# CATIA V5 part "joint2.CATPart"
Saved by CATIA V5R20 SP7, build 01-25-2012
Part number: joint2
Bounding box of the stored display mesh (mm): x 306.35 to 501.44, y -23 to 23, z 366.216 to 412.367
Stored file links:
  D:\thinkmotion-MPB\Dropbox\Pack 1 sylvain\CFAO_2010_yyang\yyang\CFAO_2010_yyang\joint2.CATPart
  D:\thinkmotion-MPB\Dropbox\Pack 1 sylvain\CFAO_2010_yyang\yyang\CFAO_2010_yyang\yyang.CATProduct
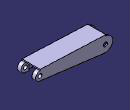
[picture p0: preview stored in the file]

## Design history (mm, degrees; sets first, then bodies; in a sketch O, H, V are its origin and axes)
External parameters (linked from other documents)
  `External.rayon du trou des liaisons` = 5 mm
  `External.rayon plus petit` = 11 mm
  `External.rayon plus grand` = 18 mm
  `External.epaisseur du joint` = 3 mm
  `External.epaisseur de l'oreille` = 3 mm
  `External.demi_distance entre les oreilles` = 15 mm
  `External.longeur du poche plus petit` = 20 mm
  `External.demi_distance entre pivots en haut` = 11 mm
  `External.epaisseur du pivot en haut` = 3 mm
  `External.epaisseur du pivot` = 2 mm
Set1
  Plane1: linked copy from another document
  Point1: linked copy from another document
  Point2: linked copy from another document
Body1 (main body)
  Sketch1 on Plane1, origin (0, 0, 0), H (-1, 0, 0), V (0, 0, 1)
    circle A1 centre (-324.3472, 384.215) radius 5
    point P1 (-324.3472, 384.215)
    reference projected point E1 (-324.3472, 384.215) from Point1
    reference projected point E2 (-324.3472, 384.215) from Point1
    circle A2 centre (-490.4395, 398.3802) radius 5
    point P2 (-490.4395, 398.3802)
    reference projected point E3 (-490.4395, 398.3802) from Point2
    reference projected point E4 (-490.4395, 398.3802) from Point2
    arc A3 centre (-324.3472, 384.215) radius 18 from (-326.6285, 366.3602) to (-323.5721, 402.1983) ccw
    point P3 (-324.3472, 384.215)
    arc A4 centre (-490.4395, 398.3802) radius 11 from (-489.9659, 409.37) to (-491.8337, 387.4689) ccw
    point P4 (-490.4395, 398.3802)
    reference projected point E5 (-490.4395, 398.3802) from Point2
    reference projected point E6 (-490.4395, 398.3802) from Point2
    reference projected point E7 (-324.3472, 384.215) from Point1
    reference projected point E8 (-324.3472, 384.215) from Point1
    axis line L1 (-489.9659, 409.37) -> (-323.5721, 402.1983)
    line L2 (-491.8337, 387.4689) -> (-326.6285, 366.3602)
    line L3 (-489.8367, 412.3672) -> (-323.4429, 405.1956)
    line L4 (-489.9659, 409.37) -> (-489.8367, 412.3672)
    line L5 (-323.5721, 402.1983) -> (-323.4429, 405.1956)
    distance A1 E2 = 5 {= `External.rayon du trou des liaisons`}
    distance A2 E4 = 5 {= `External.rayon du trou des liaisons`}
    distance A4 E6 = 11 {= `External.rayon plus petit`}
    distance A3 E8 = 18 {= `External.rayon plus grand`}
    distance L3 L1 = 3 {= `External.epaisseur du joint`}
    coincidence: P1 E1, P2 E3, P4 E5, P3 E7
    tangency: L1 A3, L1 A4, L2 A4, L2 A3
    perpendicularity: L4 L3, L5 L3
  Pad1: profile Sketch1, direction (0, 1, 0), length 23 {= `External.epaisseur du joint`+`External.epaisseur de l'oreille`+`External.demi_distance entre les oreilles`+`External.epaisseur du pivot`}, mirrored extent
  Sketch2 on Plane1, origin (0, 0, 0), H (-1, 0, 0), V (0, 0, 1)
    line L1 (-481.4395, 409.0025) -> (-481.4395, 386.1408)
    line L2 (-481.4395, 409.0025) -> (-501.4395, 409.8645)
    line L3 (-501.4395, 409.8645) -> (-501.4395, 388.6962)
    reference projected arc E1 centre (-490.4395, 398.3802) radius 11 from (-490.7705, 409.3752) to (-490.7705, 387.3851) ccw from edge [face of Pad1 from Sketch1.A4 | end face of Pad1]
    line L4 (-481.4395, 386.1408) -> (-501.4395, 388.6962)
    reference projected line E2 (-488.8457, 387.0871) -> (-324.053, 366.0311) from edge [face of Pad1 from Sketch1.L2 | end face of Pad1]
    reference projected line E3 (-321.7093, 405.1208) -> (-488.1021, 412.2924) from edge [face of Pad1 from Sketch1.L3 | end face of Pad1]
    reference projected line E4 (-321.7093, 405.1208) -> (-488.1021, 412.2924) from edge [face of Pad1 from Sketch1.L3 | end face of Pad1]
    distance L1 L3 = 20 {= `External.longeur du poche plus petit`}
    distance E4 L2 = 3 {= `External.epaisseur du joint`}
    vertical: L1 V
    tangency: L3 E1
    coincidence: L4 E2
    parallelism: E3 L2
  Pocket1: profile Sketch2, direction (0, -1, 0), length 14 {= `External.demi_distance entre pivots en haut`+`External.epaisseur du pivot en haut`}, mirrored extent
  Sketch3 on Plane1, origin (0, 0, 0), H (-1, 0, 0), V (0, 0, 1)
    line L1 (-481.4395, 409.0025) -> (-481.4395, 386.1408)
    line L2 (-481.4395, 386.1408) -> (-306.3472, 363.7688)
    line L3 (-306.3472, 363.7688) -> (-306.3472, 401.4559)
    line L4 (-306.3472, 401.4559) -> (-481.4395, 409.0025)
    reference projected arc E1 centre (-324.3472, 384.215) radius 18 from (-324.8878, 366.2232) to (-324.8878, 402.2069) ccw from edge [face of Pad1 from Sketch1.A3 | end face of Pad1]
    reference projected line E2 (-486.8623, 386.8337) -> (-321.8189, 365.7457) from edge [face of Pad1 from Sketch1.L2 | end face of Pad1]
    reference projected arc E3 centre (-490.4395, 398.3802) radius 11 from (-490.77, 409.3752) to (-490.77, 387.3851) ccw from edge [face of Pad1 from Sketch1.A4 | end face of Pad1]
    reference projected line E4 (-321.7093, 405.1208) -> (-488.1021, 412.2924) from edge [face of Pad1 from Sketch1.L3 | end face of Pad1]
    reference projected line E5 (-321.7093, 405.1208) -> (-488.1021, 412.2924) from edge [face of Pad1 from Sketch1.L3 | end face of Pad1]
    distance L1 E3 = 20 {= `External.longeur du poche plus petit`}
    distance L4 E4 = 3 {= `External.epaisseur du joint`}
    vertical: L1 V, L3 V
    tangency: L3 E1
    coincidence: L2 E2
    parallelism: L4 E5
  Pocket2: profile Sketch3, direction (0, -1, 0), length 20 {= `External.epaisseur de l'oreille`+`External.demi_distance entre les oreilles`+`External.epaisseur du pivot`}, mirrored extent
